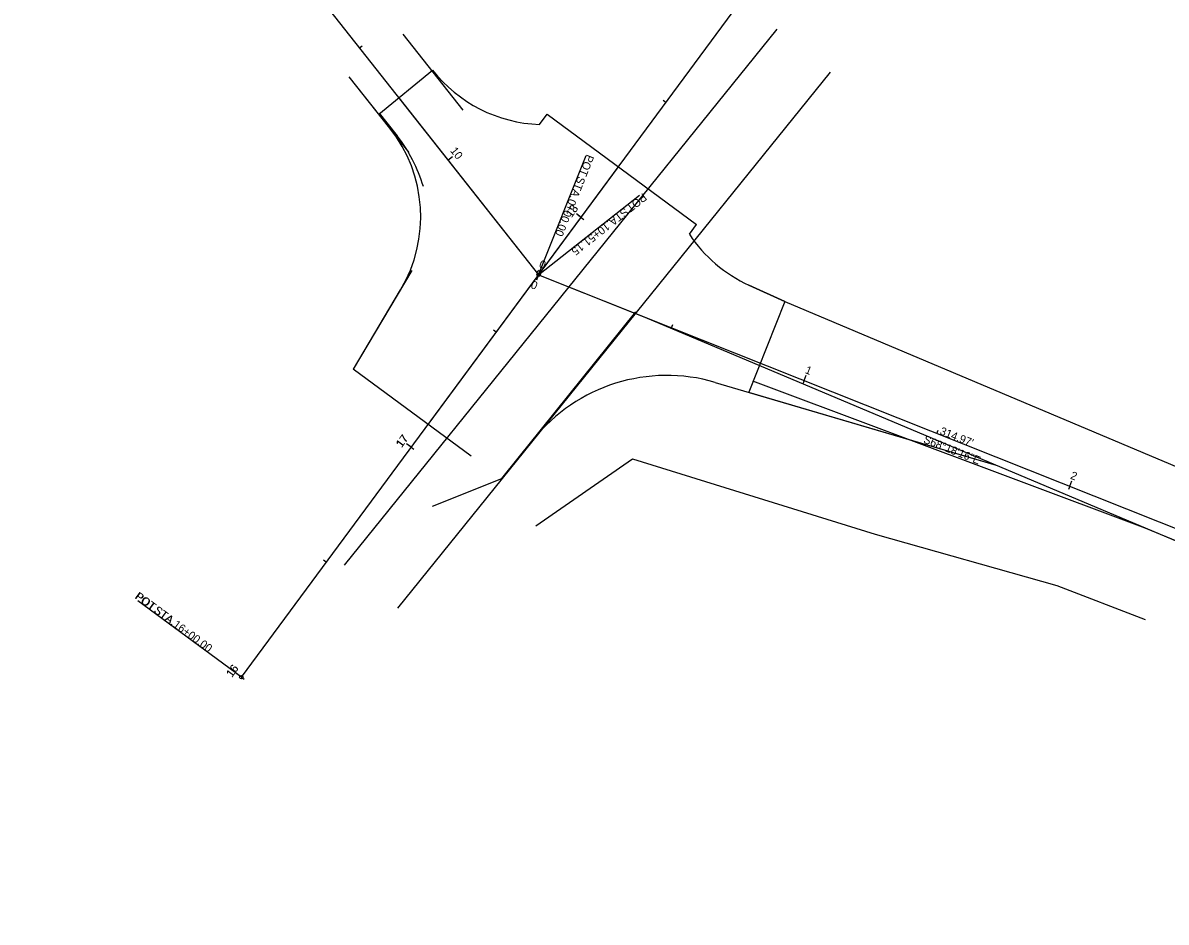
# Model space of a CAD drawing. Extents: x 1323137 to 1326838, y 458936 to 461644.
# Drawn here: x 1324820.9 to 1325220.9, y 459647 to 459961.6 of the extents above; entities that cross this region are included whole.
import ezdxf

# ---------------------------------------------------------------- set-up
doc = ezdxf.new("R2010")
doc.units = 0
for name, color, linetype in [('_CIVIL_CONSTRUCTION', 7, 'Continuous'), ('CM_Corridor_Range_Final', 7, 'Continuous'), ('Default', 7, 'Continuous'), ('DT_P_Graded_Shoulder', 7, 'Continuous'), ('DT_P_Tie', 7, 'Continuous'), ('MD_P_ACB_B', 7, 'Continuous'), ('MD_P_ACB_T', 7, 'Continuous'), ('MD_P_ACIC_B', 7, 'Continuous'), ('MD_P_ACSC_B', 7, 'Continuous'), ('MD_P_ACSC_T', 7, 'Continuous'), ('MD_P_CURB_FACE_TOP', 7, 'Continuous'), ('MD_P_Surface_Asphalt_Concrete_Intermediate_Course', 7, 'Continuous'), ('PV_P_Shoulder', 7, 'Continuous'), ('SG_P_Conduit', 7, 'Continuous'), ('SG_P_Mast_Arm', 7, 'Continuous'), ('SN_P_Signs', 7, 'Continuous'), ('SN_X_Public', 7, 'Continuous')]:
    doc.layers.add(name, color=color, linetype=linetype)

msp = doc.modelspace()

# ---------------------------------------------------------------- linework, layer by layer
at = {"layer": '_CIVIL_CONSTRUCTION'}
for p, q in [((1325001.3, 459873.43), (1325036.62, 459901.32)), ((1324897.32, 459732.7), (1324861.13, 459759.44))]:
    msp.add_line(p, q, dxfattribs=at)
for centre in [(1325001.3, 459873.43), (1324897.32, 459732.7)]:
    msp.add_circle(centre, 0.6, dxfattribs=at)
at = {"layer": 'CM_Corridor_Range_Final'}
for p, q in [((1324938.63, 459952.82), (1324939.57, 459953.57)), ((1325045.88, 459933.77), (1325044.92, 459934.48)), ((1324969.61, 459913.58), (1324971.18, 459914.82)), ((1325016.17, 459893.56), (1325014.56, 459894.75)), ((1325000.59, 459874.34), (1325001.53, 459875.08)), ((1324986.46, 459853.34), (1324985.49, 459854.06)), ((1324956.75, 459813.13), (1324955.14, 459814.32)), ((1324927.03, 459772.91), (1324926.07, 459773.63)), ((1324897.32, 459732.7), (1324895.71, 459733.89))]:
    msp.add_line(p, q, dxfattribs=at)
at = {"layer": 'Default'}
for p, q in [((1324820.87, 460101.98), (1325001.3, 459873.43)), ((1325001.32, 459873.45), (1325293.97, 459757.01))]:
    msp.add_line(p, q, dxfattribs=at)
msp.add_lwpolyline([(1325451.7, 459681.24), (1325442.79, 459685.53), (1325433.79, 459689.8), (1325424.78, 459694.02), (1325415.73, 459698.2), (1325406.67, 459702.34), (1325397.58, 459706.44), (1325388.48, 459710.51), (1325379.35, 459714.54), (1325370.21, 459718.54), (1325361.06, 459722.52), (1325351.89, 459726.48), (1325342.71, 459730.41), (1325333.52, 459734.33), (1325324.32, 459738.24), (1325315.11, 459742.13), (1325305.9, 459746.02), (1325296.69, 459749.9), (1325222.91, 459780.98), (1325213.53, 459784.78), (1325076.26, 459836.24)], dxfattribs=at)
msp.add_arc((1332431.06, 469929.07), 12277.67, 232.043309, 236.873031, dxfattribs=at)
at = {"layer": 'DT_P_Tie'}
for p, q in [((1324933.4, 459771.86), (1325084.73, 459959.43)), ((1324974.89, 459931.1), (1324953.92, 459957.65)), ((1324956.05, 459916.23), (1324935.09, 459942.78)), ((1324949.31, 459924.76), (1324935.09, 459942.78)), ((1324949.31, 459924.76), (1324935.09, 459942.78)), ((1324945.43, 459929.68), (1324964.18, 459945.09)), ((1324952.08, 459756.79), (1325103.41, 459944.36)), ((1324952.38, 459935.4), (1325001.3, 459873.43)), ((1324945.56, 459930.01), (1324951.86, 459922.08)), ((1324951.86, 459922.08), (1324945.56, 459930.01)), ((1325001.65, 459926.06), (1325004.31, 459929.67)), ((1325004.31, 459929.67), (1325056.59, 459891.05)), ((1324962.67, 459821.14), (1325029.25, 459911.25)), ((1325054.08, 459887.64), (1325056.59, 459891.05)), ((1324936.5, 459840.42), (1324957.06, 459874.97)), ((1325001.32, 459873.45), (1325033.99, 459860.45)), ((1325074.91, 459869.84), (1325087.46, 459864.07)), ((1325087.46, 459864.07), (1325074.91, 459869.84)), ((1324936.5, 459840.42), (1324953.04, 459868.22)), ((1325087.46, 459864.07), (1325074.85, 459832.37)), ((1325087.43, 459864.09), (1325301.25, 459774.02)), ((1325087.43, 459864.09), (1325301.25, 459774.02)), ((1324988.42, 459802.15), (1325035.27, 459860.51)), ((1325033.99, 459860.45), (1325078.91, 459842.58)), ((1325038.48, 459858.66), (1325291.94, 459751.9)), ((1325038.48, 459858.66), (1325291.94, 459751.9)), ((1324977.7, 459810.07), (1324936.48, 459840.43)), ((1325063.13, 459835.82), (1325161.44, 459806.87)), ((1325063.13, 459835.82), (1325161.44, 459806.87)), ((1325074.73, 459832.4), (1325161.44, 459806.87)), ((1324988.42, 459802.15), (1324999.4, 459815.82)), ((1324964.2, 459792.58), (1324988.42, 459802.15))]:
    msp.add_line(p, q, dxfattribs=at)
for centre, radius, start, end in [((1325003.46, 459976.03), 50, 218.2247, 267.9246), ((1324910.07, 459893.78), 50, 329.2512, 38.2905), ((1324910.07, 459893.78), 50, 329.2512, 38.2905), ((1324908.96, 459888.74), 54.33, 16.7055, 37.8522), ((1325095.73, 459915.3), 50, 213.5858, 245.3887), ((1325046.19, 459778.26), 60, 73.5937, 141.2431), ((1325046.19, 459778.26), 60, 73.5937, 141.2431)]:
    msp.add_arc(centre, radius, start, end, dxfattribs=at)
at = {"layer": 'MD_P_ACB_B'}
for p, q in [((1325001.32, 459873.45), (1325017.95, 459915.26)), ((1324897.32, 459732.7), (1324861.13, 459759.44))]:
    msp.add_line(p, q, dxfattribs=at)
for centre in [(1325001.32, 459873.45), (1324897.32, 459732.7)]:
    msp.add_circle(centre, 0.6, dxfattribs=at)
at = {"layer": 'MD_P_ACSC_B'}
for p, q in [((1325001.32, 459873.45), (1325017.95, 459915.26)), ((1324897.32, 459732.7), (1324861.13, 459759.44))]:
    msp.add_line(p, q, dxfattribs=at)
for centre in [(1325001.32, 459873.45), (1324897.32, 459732.7)]:
    msp.add_circle(centre, 0.6, dxfattribs=at)
at = {"layer": 'MD_P_CURB_FACE_TOP'}
for p, q in [((1325000.33, 459785.66), (1325034.13, 459809.13)), ((1325034.13, 459809.13), (1325119.04, 459782.76)), ((1325119.04, 459782.76), (1325182.61, 459764.82)), ((1325182.61, 459764.82), (1325213.57, 459752.93))]:
    msp.add_line(p, q, dxfattribs=at)
at = {"layer": 'MD_P_Surface_Asphalt_Concrete_Intermediate_Course'}
for p, q in [((1325001.3, 459873.43), (1325036.62, 459901.32)), ((1324897.32, 459732.7), (1324861.13, 459759.44))]:
    msp.add_line(p, q, dxfattribs=at)
for centre in [(1325001.3, 459873.43), (1324897.32, 459732.7)]:
    msp.add_circle(centre, 0.6, dxfattribs=at)
at = {"layer": 'PV_P_Shoulder'}
for p, q in [((1325016.17, 459893.56), (1325017.14, 459892.84)), ((1325001.32, 459873.45), (1325000.58, 459871.59)), ((1325094.23, 459836.48), (1325093.79, 459835.37)), ((1324956.75, 459813.13), (1324957.71, 459812.42)), ((1325187.15, 459799.51), (1325186.7, 459798.4)), ((1324897.32, 459732.7), (1324898.29, 459731.99))]:
    msp.add_line(p, q, dxfattribs=at)
at = {"layer": 'SG_P_Conduit'}
for p, q in [((1324897.32, 459732.7), (1325580.71, 460657.62)), ((1325001.32, 459873.45), (1325293.97, 459757.01))]:
    msp.add_line(p, q, dxfattribs=at)
at = {"layer": 'SG_P_Mast_Arm'}
for p, q in [((1325045.88, 459933.77), (1325044.92, 459934.48)), ((1325016.17, 459893.56), (1325014.56, 459894.75)), ((1325001.32, 459873.45), (1325002.05, 459875.31)), ((1324986.46, 459853.34), (1324985.49, 459854.06)), ((1325047.77, 459854.97), (1325048.22, 459856.08)), ((1325094.23, 459836.48), (1325094.97, 459838.34)), ((1325140.69, 459818), (1325141.13, 459819.11)), ((1324956.75, 459813.13), (1324955.14, 459814.32)), ((1325187.15, 459799.51), (1325187.89, 459801.37)), ((1324927.03, 459772.91), (1324926.07, 459773.63)), ((1324897.32, 459732.7), (1324895.71, 459733.89))]:
    msp.add_line(p, q, dxfattribs=at)
at = {"layer": 'SN_P_Signs'}
for p, q in [((1324897.32, 459732.7), (1325551, 460617.41)), ((1324820.87, 460101.98), (1325001.3, 459873.43)), ((1325001.32, 459873.45), (1325293.97, 459757.01))]:
    msp.add_line(p, q, dxfattribs=at)
msp.add_arc((1332431.06, 469929.07), 12277.67, 232.043309, 236.873031, dxfattribs=at)
at = {"layer": 'SN_X_Public'}
for p, q in [((1324969.61, 459913.58), (1324971.18, 459914.82)), ((1325016.17, 459893.56), (1325015.21, 459894.27)), ((1324956.75, 459813.13), (1324955.78, 459813.84)), ((1324897.32, 459732.7), (1324896.36, 459733.41))]:
    msp.add_line(p, q, dxfattribs=at)

# ---------------------------------------------------------------- texts
at = {"layer": '_CIVIL_CONSTRUCTION'}
for s, rotation, p in [('POT', 218.2905, (1325037.76, 459902.17)), (' STA. ', 218.2905, (1325032.17, 459897.75)), ('10+51.15', 218.2905, (1325024.85, 459891.98)), ('POT', 323.5406, (1324859.96, 459760.35)), (' STA. ', 323.5406, (1324865.69, 459756.12)), ('16+00.00', 323.5406, (1324873.19, 459750.58))]:
    msp.add_text(s, height=2.8, rotation=rotation, dxfattribs=at).set_placement(p)
at = {"layer": 'CM_Corridor_Range_Final'}
for s, rotation, p in [('10', 308.2905, (1324970.24, 459916.82)), ('18', 53.5406, (1325012.89, 459893.33)), ('17', 53.5406, (1324953.47, 459812.9)), ('16', 53.5406, (1324894.04, 459732.47))]:
    msp.add_text(s, height=2.8, rotation=rotation, dxfattribs=at).set_placement(p)
at = {"layer": 'DT_P_Graded_Shoulder'}
msp.add_text('S68°18\'16"E', height=2.8, rotation=338.3044, dxfattribs=at).set_placement((1325135.7, 459814.82))
at = {"layer": 'MD_P_ACB_B'}
for s, rotation, p in [('POT', 248.3044, (1325018.2, 459915.77)), (' STA. ', 248.3044, (1325015.54, 459909.08)), ('0+00.00', 248.3044, (1325012.04, 459900.3)), ('POT', 323.5406, (1324859.8, 459760.48)), (' STA. ', 323.5406, (1324865.59, 459756.2)), ('16+00.00', 323.5406, (1324873.19, 459750.58))]:
    msp.add_text(s, height=2.8, rotation=rotation, dxfattribs=at).set_placement(p)
at = {"layer": 'MD_P_ACB_T'}
msp.add_text("314.97'", height=2.8, rotation=338.3044, dxfattribs=at).set_placement((1325141.45, 459817.74))
at = {"layer": 'MD_P_ACIC_B'}
msp.add_text('S68°18\'16"E', height=2.8, rotation=338.3044, dxfattribs=at).set_placement((1325135.7, 459814.82))
at = {"layer": 'MD_P_ACSC_B'}
for s, rotation, p in [('POT', 248.3044, (1325018.2, 459915.77)), (' STA. ', 248.3044, (1325015.54, 459909.08)), ('0+00.00', 248.3044, (1325012.04, 459900.3)), ('POT', 323.5406, (1324859.8, 459760.48)), (' STA. ', 323.5406, (1324865.59, 459756.2)), ('16+00.00', 323.5406, (1324873.19, 459750.58))]:
    msp.add_text(s, height=2.8, rotation=rotation, dxfattribs=at).set_placement(p)
at = {"layer": 'MD_P_ACSC_T'}
msp.add_text("314.97'", height=2.8, rotation=338.3044, dxfattribs=at).set_placement((1325141.45, 459817.74))
at = {"layer": 'MD_P_Surface_Asphalt_Concrete_Intermediate_Course'}
for s, rotation, p in [('POT', 218.2905, (1325037.76, 459902.17)), (' STA. ', 218.2905, (1325032.17, 459897.75)), ('10+51.15', 218.2905, (1325024.85, 459891.98)), ('POT', 323.5406, (1324859.96, 459760.35)), (' STA. ', 323.5406, (1324865.69, 459756.12)), ('16+00.00', 323.5406, (1324873.19, 459750.58))]:
    msp.add_text(s, height=2.8, rotation=rotation, dxfattribs=at).set_placement(p)
at = {"layer": 'PV_P_Shoulder'}
msp.add_text('0', height=2.8, rotation=338.3044, dxfattribs=at).set_placement((1324998.32, 459868.94))
at = {"layer": 'SG_P_Mast_Arm'}
for s, rotation, p in [('18', 53.5406, (1325012.84, 459893.26)), ('0', 338.3044, (1325001.21, 459876.18)), ('1', 338.3044, (1325094.3, 459839.14)), ('17', 53.5406, (1324953.37, 459812.77)), ('2', 338.3044, (1325187.1, 459802.22)), ('16', 53.5406, (1324893.98, 459732.38))]:
    msp.add_text(s, height=2.8, rotation=rotation, dxfattribs=at).set_placement(p)
at = {"layer": 'SN_X_Public'}
msp.add_text('10', height=2.8, rotation=308.2905, dxfattribs=at).set_placement((1324970.24, 459916.82))

doc.saveas('drawing.dxf')
